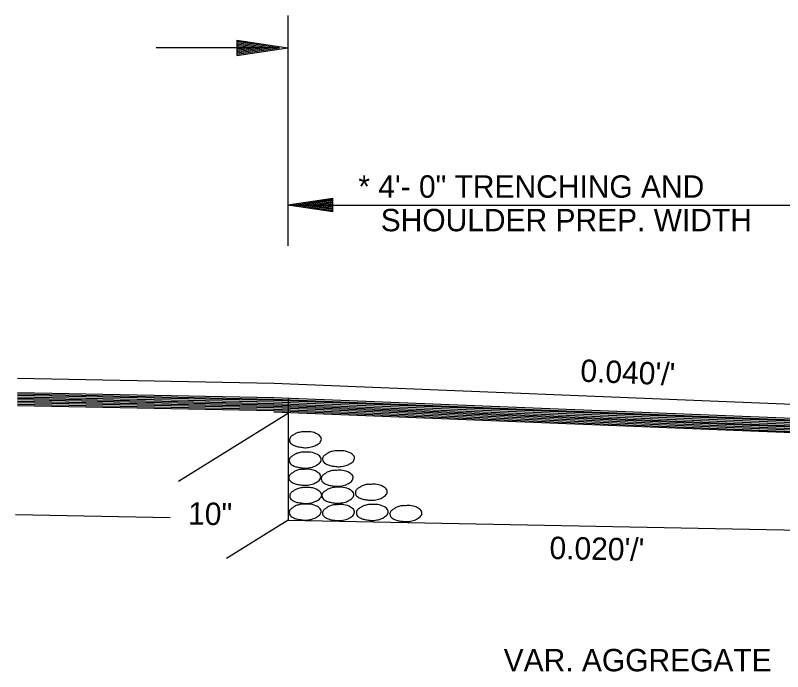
# Model space of a CAD drawing. Extents: x 1931522 to 1935523, y 600380 to 605075.
# Drawn here: x 1933188 to 1933393.5, y 604271.5 to 604447.4 of the extents above; entities that cross this region are included whole.
import ezdxf

# ---------------------------------------------------------------- set-up
doc = ezdxf.new("R2010")
doc.units = 0
doc.layers.add('Default', color=7, linetype='Continuous')

msp = doc.modelspace()

# ---------------------------------------------------------------- linework, layer by layer
at = {"layer": 'Default'}
for p, q in [((1933261.04, 604447.37), (1933261.04, 604385.6)), ((1933247.32, 604440.74), (1933261.02, 604438.7)), ((1933247.32, 604440.74), (1933247.32, 604436.64)), ((1933247.32, 604440.41), (1933258.75, 604438.7)), ((1933247.32, 604440.06), (1933256.38, 604438.7)), ((1933258.75, 604438.7), (1933225.72, 604438.7)), ((1933247.32, 604439.73), (1933254.1, 604438.7)), ((1933247.32, 604439.34), (1933251.78, 604438.7)), ((1933247.32, 604439.03), (1933249.51, 604438.7)), ((1933247.32, 604436.64), (1933261.02, 604438.7)), ((1933247.32, 604438.02), (1933251.78, 604438.7)), ((1933247.32, 604437.33), (1933256.38, 604438.7)), ((1933247.32, 604436.99), (1933258.75, 604438.7)), ((1933247.32, 604437.69), (1933254.1, 604438.7)), ((1933247.32, 604438.37), (1933249.51, 604438.7)), ((1933273.04, 604398.31), (1933261.04, 604396.51)), ((1933273.04, 604398.01), (1933263.04, 604396.51)), ((1933273.04, 604397.7), (1933265.11, 604396.51)), ((1933273.04, 604397.4), (1933267.11, 604396.51)), ((1933273.04, 604397.1), (1933269.14, 604396.51)), ((1933273.04, 604394.71), (1933273.04, 604398.31)), ((1933261.04, 604396.51), (1933439.74, 604396.51)), ((1933273.04, 604394.71), (1933261.04, 604396.51)), ((1933273.04, 604395.01), (1933263.04, 604396.51)), ((1933273.04, 604395.32), (1933265.11, 604396.51)), ((1933273.04, 604395.62), (1933267.11, 604396.51)), ((1933273.04, 604395.93), (1933269.14, 604396.51)), ((1933273.04, 604396.79), (1933271.14, 604396.51)), ((1933273.04, 604396.23), (1933271.14, 604396.51)), ((1933188.61, 604350.13), (1933257.22, 604348.76)), ((1933257.22, 604348.76), (1933439.61, 604341.45)), ((1933188.61, 604346.31), (1933257.22, 604344.96)), ((1933188.61, 604345.89), (1933257.22, 604344.52)), ((1933188.61, 604345.57), (1933257.22, 604344.19)), ((1933188.61, 604345.16), (1933257.22, 604343.77)), ((1933188.61, 604344.76), (1933257.22, 604343.35)), ((1933188.61, 604344.38), (1933257.22, 604342.99)), ((1933188.61, 604343.99), (1933257.22, 604342.61)), ((1933188.61, 604343.6), (1933257.22, 604342.23)), ((1933257.22, 604344.96), (1933439.45, 604337.63)), ((1933257.22, 604344.52), (1933439.73, 604337.18)), ((1933257.22, 604344.19), (1933439.92, 604336.89)), ((1933257.22, 604343.77), (1933440.23, 604336.43)), ((1933261.14, 604344.81), (1933261.14, 604312.09)), ((1933188.61, 604343.17), (1933257.22, 604341.81)), ((1933188.61, 604342.79), (1933257.22, 604341.44)), ((1933257.22, 604343.35), (1933440.45, 604336.03)), ((1933257.22, 604342.99), (1933440.73, 604335.59)), ((1933257.22, 604342.61), (1933440.95, 604335.25)), ((1933257.22, 604342.23), (1933441.27, 604334.81)), ((1933257.22, 604341.81), (1933441.51, 604334.41)), ((1933257.22, 604341.44), (1933441.77, 604333.97)), ((1933261.18, 604340.75), (1933231.75, 604322.42)), ((1933257.22, 604341.11), (1933441.94, 604333.69)), ((1933188.03, 604313.57), (1933229.52, 604312.74)), ((1933261.14, 604312.09), (1933244.6, 604301.79)), ((1933261.14, 604312.09), (1933664.05, 604304.05))]:
    msp.add_line(p, q, dxfattribs=at)
for points in [[(1933265.64, 604335.75), (1933267.17, 604335.74), (1933268.99, 604335.1), (1933269.88, 604334.27), (1933270, 604333.73), (1933269.54, 604332.81), (1933269.02, 604332.42), (1933268.02, 604331.9), (1933266.56, 604331.56), (1933265.8, 604331.48), (1933264.69, 604331.59), (1933263.43, 604331.8), (1933262.48, 604332.17), (1933261.6, 604332.9), (1933261.45, 604333.48), (1933261.71, 604334.3), (1933262.41, 604334.83), (1933263.05, 604335.25), (1933264.07, 604335.6), (1933264.7, 604335.74), (1933265.64, 604335.75)], [(1933265.59, 604330.27), (1933267.12, 604330.26), (1933268.94, 604329.62), (1933269.83, 604328.79), (1933269.95, 604328.25), (1933269.49, 604327.33), (1933268.97, 604326.94), (1933267.97, 604326.42), (1933266.51, 604326.08), (1933265.75, 604326), (1933264.64, 604326.11), (1933263.38, 604326.32), (1933262.43, 604326.69), (1933261.55, 604327.42), (1933261.4, 604328), (1933261.66, 604328.82), (1933262.36, 604329.35), (1933263, 604329.77), (1933264.02, 604330.12), (1933264.65, 604330.26), (1933265.59, 604330.27)], [(1933274.5, 604330.65), (1933276.03, 604330.64), (1933277.85, 604330), (1933278.74, 604329.17), (1933278.86, 604328.63), (1933278.4, 604327.71), (1933277.88, 604327.32), (1933276.88, 604326.8), (1933275.42, 604326.46), (1933274.66, 604326.38), (1933273.55, 604326.49), (1933272.29, 604326.7), (1933271.34, 604327.07), (1933270.46, 604327.8), (1933270.31, 604328.38), (1933270.57, 604329.2), (1933271.27, 604329.73), (1933271.91, 604330.15), (1933272.93, 604330.5), (1933273.56, 604330.64), (1933274.5, 604330.65)], [(1933265.47, 604325.67), (1933267, 604325.66), (1933268.82, 604325.02), (1933269.71, 604324.19), (1933269.83, 604323.65), (1933269.37, 604322.73), (1933268.85, 604322.34), (1933267.85, 604321.82), (1933266.39, 604321.48), (1933265.63, 604321.4), (1933264.52, 604321.51), (1933263.26, 604321.72), (1933262.31, 604322.09), (1933261.43, 604322.82), (1933261.28, 604323.4), (1933261.54, 604324.22), (1933262.24, 604324.75), (1933262.88, 604325.17), (1933263.9, 604325.52), (1933264.53, 604325.66), (1933265.47, 604325.67)], [(1933274.14, 604325.4), (1933275.67, 604325.39), (1933277.49, 604324.75), (1933278.38, 604323.92), (1933278.5, 604323.38), (1933278.04, 604322.46), (1933277.52, 604322.07), (1933276.52, 604321.55), (1933275.06, 604321.21), (1933274.3, 604321.13), (1933273.19, 604321.24), (1933271.93, 604321.45), (1933270.98, 604321.82), (1933270.1, 604322.55), (1933269.95, 604323.13), (1933270.21, 604323.95), (1933270.91, 604324.48), (1933271.55, 604324.9), (1933272.57, 604325.25), (1933273.2, 604325.39), (1933274.14, 604325.4)], [(1933265.72, 604320.78), (1933267.25, 604320.77), (1933269.07, 604320.13), (1933269.96, 604319.3), (1933270.08, 604318.76), (1933269.62, 604317.84), (1933269.1, 604317.45), (1933268.1, 604316.93), (1933266.64, 604316.59), (1933265.88, 604316.51), (1933264.77, 604316.62), (1933263.51, 604316.83), (1933262.56, 604317.2), (1933261.68, 604317.93), (1933261.53, 604318.51), (1933261.79, 604319.33), (1933262.49, 604319.86), (1933263.13, 604320.28), (1933264.15, 604320.63), (1933264.78, 604320.77), (1933265.72, 604320.78)], [(1933274.33, 604320.86), (1933275.86, 604320.85), (1933277.68, 604320.21), (1933278.57, 604319.38), (1933278.69, 604318.84), (1933278.23, 604317.92), (1933277.71, 604317.53), (1933276.71, 604317.01), (1933275.25, 604316.67), (1933274.49, 604316.59), (1933273.38, 604316.7), (1933272.12, 604316.91), (1933271.17, 604317.28), (1933270.29, 604318.01), (1933270.14, 604318.59), (1933270.4, 604319.41), (1933271.1, 604319.94), (1933271.74, 604320.36), (1933272.76, 604320.71), (1933273.39, 604320.85), (1933274.33, 604320.86)], [(1933283.29, 604321.65), (1933284.82, 604321.64), (1933286.64, 604321), (1933287.53, 604320.17), (1933287.65, 604319.63), (1933287.19, 604318.71), (1933286.67, 604318.32), (1933285.67, 604317.8), (1933284.21, 604317.46), (1933283.45, 604317.38), (1933282.34, 604317.49), (1933281.08, 604317.7), (1933280.13, 604318.07), (1933279.25, 604318.8), (1933279.1, 604319.38), (1933279.36, 604320.2), (1933280.06, 604320.73), (1933280.7, 604321.15), (1933281.72, 604321.5), (1933282.35, 604321.64), (1933283.29, 604321.65)], [(1933265.57, 604316.34), (1933267.1, 604316.33), (1933268.92, 604315.69), (1933269.81, 604314.86), (1933269.93, 604314.32), (1933269.47, 604313.4), (1933268.95, 604313.01), (1933267.95, 604312.49), (1933266.49, 604312.15), (1933265.73, 604312.07), (1933264.62, 604312.18), (1933263.36, 604312.39), (1933262.41, 604312.76), (1933261.53, 604313.49), (1933261.38, 604314.07), (1933261.64, 604314.89), (1933262.34, 604315.42), (1933262.98, 604315.84), (1933264, 604316.19), (1933264.63, 604316.33), (1933265.57, 604316.34)], [(1933274.49, 604316.2), (1933276.02, 604316.19), (1933277.84, 604315.55), (1933278.73, 604314.72), (1933278.85, 604314.18), (1933278.39, 604313.26), (1933277.87, 604312.87), (1933276.87, 604312.35), (1933275.41, 604312.01), (1933274.65, 604311.93), (1933273.54, 604312.04), (1933272.28, 604312.25), (1933271.33, 604312.62), (1933270.45, 604313.35), (1933270.3, 604313.93), (1933270.56, 604314.75), (1933271.26, 604315.28), (1933271.9, 604315.7), (1933272.92, 604316.05), (1933273.55, 604316.19), (1933274.49, 604316.2)], [(1933283.56, 604316.25), (1933285.09, 604316.24), (1933286.91, 604315.6), (1933287.8, 604314.77), (1933287.92, 604314.23), (1933287.46, 604313.31), (1933286.94, 604312.92), (1933285.94, 604312.4), (1933284.48, 604312.06), (1933283.72, 604311.98), (1933282.61, 604312.09), (1933281.35, 604312.3), (1933280.4, 604312.67), (1933279.52, 604313.4), (1933279.37, 604313.98), (1933279.63, 604314.8), (1933280.33, 604315.33), (1933280.97, 604315.75), (1933281.99, 604316.1), (1933282.62, 604316.24), (1933283.56, 604316.25)], [(1933292.55, 604315.93), (1933294.08, 604315.92), (1933295.9, 604315.28), (1933296.79, 604314.45), (1933296.91, 604313.91), (1933296.45, 604312.99), (1933295.93, 604312.6), (1933294.93, 604312.08), (1933293.47, 604311.74), (1933292.71, 604311.66), (1933291.6, 604311.77), (1933290.34, 604311.98), (1933289.39, 604312.35), (1933288.51, 604313.08), (1933288.36, 604313.66), (1933288.62, 604314.48), (1933289.32, 604315.01), (1933289.96, 604315.43), (1933290.98, 604315.78), (1933291.61, 604315.92), (1933292.55, 604315.93)]]:
    msp.add_spline(points, degree=3, dxfattribs=at)

# ---------------------------------------------------------------- texts
for s, p in [('* 4\'- 0" TRENCHING AND ', (1933279.89, 604398.49)), ('SHOULDER PREP. WIDTH ', (1933285.89, 604389.49)), ('VAR. AGGREGATE', (1933318.82, 604271.54))]:
    msp.add_text(s, height=6, dxfattribs=at).set_placement(p)
for s, rotation, p in [("0.040'/'", 357.7077, (1933339.28, 604349.18)), ('10"', 358.8543, (1933234.26, 604310.89)), ("0.020'/'", 358.8543, (1933331.05, 604301.67))]:
    msp.add_text(s, height=6, rotation=rotation, dxfattribs=at).set_placement(p)

doc.saveas('drawing.dxf')
